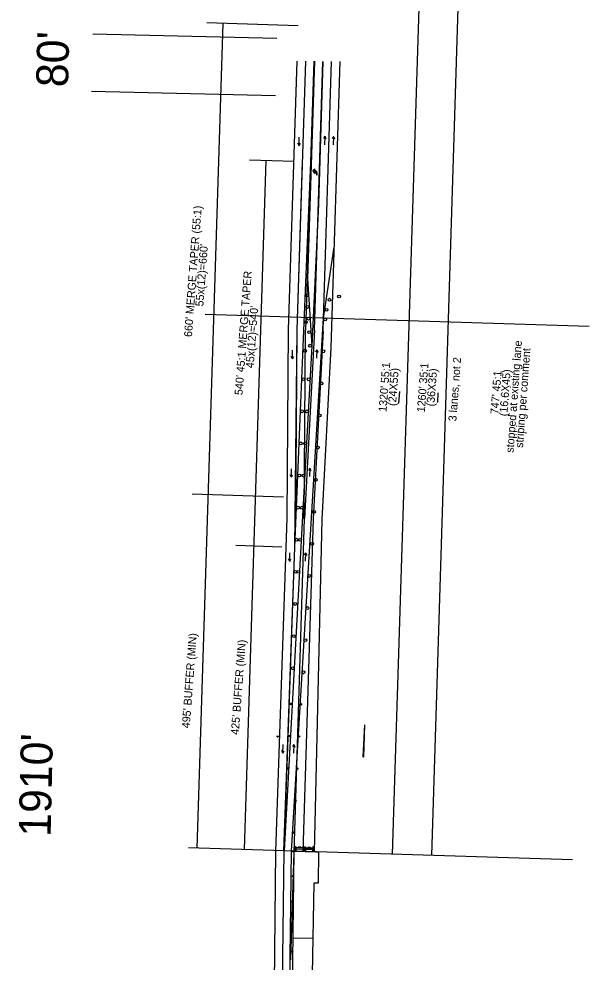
# Model space of a CAD drawing. Extents: x 1650647 to 1653016, y 602856 to 611467.
# Drawn here: x 1652184 to 1652982, y 608492 to 609813 of the extents above; entities that cross this region are included whole.
import ezdxf

# ---------------------------------------------------------------- set-up
doc = ezdxf.new("R2010")
doc.units = 0
for name, color, linetype in [('CM_Corridor_Design', 7, 'Continuous'), ('DT_X_Break_Line', 7, 'Continuous'), ('DT_X_Contour_Major', 7, 'Continuous'), ('DT_X_Void', 7, 'Continuous'), ('GE_P_Alignment_500_Bearings', 7, 'Continuous'), ('GE_P_Alignment_500_Stations', 7, 'Continuous'), ('PF_P_Grade_Line', 7, 'Continuous'), ('PF_X_Ground_Line', 7, 'Continuous'), ('PF_X_Ground_Line_LT', 7, 'Continuous'), ('PF_X_Ground_Line_RT', 7, 'Continuous'), ('PV_P_Curb', 7, 'Continuous'), ('PV_P_EOP', 7, 'Continuous'), ('PV_X_EOP', 7, 'Continuous'), ('SC_ProfileRun2', 7, 'Continuous'), ('SC_Scratch1', 7, 'Continuous'), ('UT_X_Water', 7, 'Continuous')]:
    doc.layers.add(name, color=color, linetype=linetype)

msp = doc.modelspace()

# ---------------------------------------------------------------- linework, layer by layer
at = {"layer": 'CM_Corridor_Design'}
for p, q in [((1652576.1, 609635.2), (1652576.3, 609647.1)), ((1652612, 609648.4), (1652610.1, 609645.1)), ((1652612, 609648.4), (1652611.5, 609636.5)), ((1652612, 609648.4), (1652613.6, 609644.9)), ((1652624.3, 609648.2), (1652622.4, 609644.9)), ((1652624.3, 609648.2), (1652623.8, 609636.3)), ((1652624.3, 609648.2), (1652625.9, 609644.8)), ((1652576.1, 609635.2), (1652574.4, 609638.6)), ((1652576.1, 609635.2), (1652577.9, 609638.6)), ((1652566.9, 609336.8), (1652565.2, 609340.2)), ((1652566.9, 609336.8), (1652566.8, 609348.7)), ((1652566.9, 609336.8), (1652568.6, 609340.2)), ((1652601, 609349.4), (1652599.2, 609346.1)), ((1652601, 609349.4), (1652600.5, 609337.6)), ((1652601, 609349.4), (1652602.6, 609346)), ((1652565.4, 609171.1), (1652565.3, 609182.9)), ((1652591.2, 609183.9), (1652589.3, 609180.6)), ((1652591.2, 609183.9), (1652590.7, 609172)), ((1652591.2, 609183.9), (1652592.8, 609180.4)), ((1652565.4, 609171.1), (1652563.7, 609174.4)), ((1652565.4, 609171.1), (1652567.1, 609174.5)), ((1652563, 609053.2), (1652563.4, 609065.1)), ((1652585.3, 609065.1), (1652583.4, 609061.8)), ((1652585.3, 609065.1), (1652584.8, 609053.3)), ((1652585.3, 609065.1), (1652586.9, 609061.7)), ((1652563, 609053.2), (1652561.4, 609056.7)), ((1652563, 609053.2), (1652564.8, 609056.6)), ((1652553.5, 608784.8), (1652554, 608796.7)), ((1652568.8, 608796.8), (1652566.9, 608793.5)), ((1652568.8, 608796.8), (1652568.3, 608784.9)), ((1652568.8, 608796.8), (1652570.4, 608793.3)), ((1652553.5, 608784.8), (1652551.9, 608788.3)), ((1652553.5, 608784.8), (1652555.4, 608788.2))]:
    msp.add_line(p, q, dxfattribs=at)
at = {"layer": 'DT_X_Break_Line'}
for centre, radius in [((1652587.1, 609425.7), 2), ((1652618.7, 609419.6), 2), ((1652632.1, 609424.1), 2), ((1652588.1, 609409.4), 2), ((1652614.4, 609405.4), 2), ((1652589.1, 609393.1), 2), ((1652612.5, 609392), 2), ((1652585.5, 609388.1), 2), ((1652590.3, 609374.1), 2), ((1652591.5, 609355.1), 2), ((1652584.3, 609348.2), 2), ((1652610, 609347.3), 2), ((1652582.1, 609308.3), 2), ((1652589.6, 609308.1), 2), ((1652607.4, 609302.4), 2), ((1652580.2, 609263.4), 2), ((1652587.2, 609263.2), 2), ((1652604.8, 609257.4), 2), ((1652578.4, 609218.4), 2), ((1652584.8, 609218.2), 2), ((1652602.2, 609212.5), 2), ((1652576.5, 609173.4), 2), ((1652582.3, 609173.3), 2), ((1652599.5, 609167.6), 2), ((1652574.6, 609128.5), 2), ((1652579.9, 609128.3), 2), ((1652596.9, 609122.6), 2), ((1652572.6, 609083.5), 2), ((1652577.5, 609083.4), 2), ((1652594.3, 609077.7), 2), ((1652571.1, 609038.6), 2), ((1652575, 609038.5), 2), ((1652590.3, 609032.8), 2), ((1652570.7, 608993.6), 2), ((1652587.7, 608987.9), 2), ((1652568.8, 608948.6), 2), ((1652585, 608942.9), 2), ((1652567.2, 608903.6), 2), ((1652582.4, 608898), 2), ((1652564.5, 608853.6), 1), ((1652578.7, 608853.1), 1), ((1652562.5, 608808.6), 1), ((1652576.2, 608808.2), 1), ((1652560.5, 608763.7), 1), ((1652573.5, 608763.2), 1), ((1652558.4, 608718.7), 1), ((1652570.9, 608718.3), 1), ((1652568.2, 608673.4), 1), ((1652567.8, 608647.5), 1), ((1652567.4, 608612.5), 1), ((1652567, 608577.5), 1), ((1652566.6, 608542.5), 1), ((1652566.2, 608507.5), 1)]:
    msp.add_circle(centre, radius, dxfattribs=at)
at = {"layer": 'DT_X_Contour_Major'}
msp.add_line((1652595.2, 608525.2), (1652567.8, 608525.6), dxfattribs=at)
msp.add_lwpolyline([(1652553.1, 607306.6), (1652569.1, 608647.5), (1652599.4, 608646.6), (1652603.4, 608646.5), (1652602.8, 608602.7), (1652596.7, 608602.8), (1652594.3, 608475.1)], dxfattribs=at)
at = {"layer": 'DT_X_Void'}
for p, q in [((1652598.3, 609602.3), (1652595.2, 609599.9)), ((1652597.5, 609600.1), (1652598.3, 609602.3)), ((1652598.3, 609602.3), (1652598.3, 609602.3)), ((1652595.2, 609599.9), (1652597.7, 609596.3)), ((1652598.2, 609600.1), (1652597.5, 609600.1)), ((1652597.7, 609596.3), (1652597.5, 609598.5)), ((1652597.5, 609598.5), (1652598.2, 609598.5)), ((1652598, 609594.3), (1652598, 609594.3)), ((1652600.4, 609596.1), (1652600.3, 609594.2)), ((1652600.3, 609594.2), (1652601.3, 609594.2)), ((1652601.3, 609594.2), (1652601.4, 609596.7)), ((1652581.8, 608652.1), (1652571.8, 608652.2)), ((1652574.8, 608653.7), (1652578.8, 608653.6)), ((1652575.8, 608652.2), (1652575.8, 608653.7)), ((1652576.8, 608651.2), (1652576.8, 608651.2)), ((1652577.8, 608652.2), (1652577.8, 608653.7)), ((1652595.2, 608651.7), (1652585.2, 608651.8)), ((1652588.2, 608653.3), (1652592.2, 608653.2)), ((1652589.2, 608651.8), (1652589.2, 608653.3)), ((1652591.2, 608651.7), (1652591.2, 608653.2)), ((1652581.8, 608650.1), (1652571.8, 608650.2)), ((1652595.1, 608649.7), (1652585.1, 608649.8)), ((1652590.1, 608650.8), (1652590.1, 608650.8))]:
    msp.add_line(p, q, dxfattribs=at)
for points in [[(1652570.8, 608648.2), (1652570.8, 608654.2), (1652571.8, 608654.2), (1652571.8, 608648.2)], [(1652582.8, 608648.1), (1652582.8, 608654.1), (1652581.8, 608654.1), (1652581.8, 608648.1)], [(1652584.1, 608647.8), (1652584.2, 608653.8), (1652585.2, 608653.8), (1652585.1, 608647.8)], [(1652596.1, 608647.7), (1652596.2, 608653.7), (1652595.2, 608653.7), (1652595.1, 608647.7)]]:
    msp.add_lwpolyline(points, close=True, dxfattribs=at)
for centre, radius, end in [((1652598.1, 609596.8), 3.28, 88.8321), ((1652598.1, 609596.2), 2.3, 87.9236)]:
    msp.add_arc(centre, radius, 357.9236, end, dxfattribs=at)
at = {"layer": 'GE_P_Alignment_500_Bearings'}
for p, q in [((1652588.5, 609448.9), (1652598, 609753.4)), ((1652594.5, 609355), (1652588.5, 609448.9)), ((1652555.8, 608648), (1652594.5, 609355))]:
    msp.add_line(p, q, dxfattribs=at)
for points in [[(1652570.2, 609072.8), (1652592.6, 609612.3), (1652597, 609753.4)], [(1652554.8, 608648), (1652560.7, 608815.3), (1652570.2, 609072.8)]]:
    msp.add_lwpolyline(points, dxfattribs=at)
at = {"layer": 'GE_P_Alignment_500_Stations'}
msp.add_line((1652594.5, 609355), (1652603.8, 609553.2), dxfattribs=at)
msp.add_lwpolyline([(1652570.2, 609072.7), (1652573.3, 609377.2), (1652580.9, 609612.7)], dxfattribs=at)
at = {"layer": 'PF_P_Grade_Line'}
for p, q in [((1652573.3, 609377.2), (1652585.5, 609753.5)), ((1652609.8, 609377.1), (1652621.5, 609753)), ((1652571.7, 609113.5), (1652573.3, 609377.2)), ((1652596.4, 609112.7), (1652610.3, 609376.1)), ((1652555.3, 608647.1), (1652571.7, 609113.5)), ((1652581.9, 608647.2), (1652596.4, 609112.7))]:
    msp.add_line(p, q, dxfattribs=at)
at = {"layer": 'PF_X_Ground_Line'}
for p, q in [((1652547.6, 608808.1), (1652544.4, 608808.2)), ((1652546, 608808.2), (1652545.9, 608806.6)), ((1652546, 608808.2), (1652546, 608808.2))]:
    msp.add_line(p, q, dxfattribs=at)
at = {"layer": 'PF_X_Ground_Line_LT'}
msp.add_line((1652585.8, 609377.1), (1652597.5, 609753.3), dxfattribs=at)
at = {"layer": 'PF_X_Ground_Line_RT'}
for p, q in [((1652707.1, 608643.3), (1652748.3, 609962.6)), ((1652761.8, 608641.6), (1652801.2, 609901)), ((1652433.6, 608651.8), (1652469.7, 609806.2)), ((1652575, 609803), (1652446.9, 609807)), ((1652569.1, 609613.1), (1652506.9, 609615)), ((1652499.7, 608649.8), (1652529.9, 609614.3)), ((1652982.1, 609382.1), (1652444.8, 609398.9)), ((1652715.7, 609274.7), (1652717.1, 609291.1)), ((1652770.4, 609275.5), (1652770.6, 609289.3)), ((1652554.4, 609143.3), (1652426.3, 609147.3)), ((1652552.2, 609073.3), (1652487.6, 609075.4)), ((1652665.6, 608779.4), (1652668.2, 608824.3)), ((1652666.6, 608779.3), (1652668.2, 608824.3)), ((1652666.6, 608779.3), (1652665.6, 608779.4)), ((1652958.8, 608635.4), (1652421.5, 608652.2))]:
    msp.add_line(p, q, dxfattribs=at)
at = {"layer": 'PV_P_Curb'}
for p, q in [((1652583.4, 609113.3), (1652585.3, 609377.1)), ((1652584.4, 609113.3), (1652598.3, 609376.7)), ((1652564.6, 608495.4), (1652583.9, 609113.3))]:
    msp.add_line(p, q, dxfattribs=at)
at = {"layer": 'PV_P_EOP'}
for p, q in [((1652603.8, 609553.2), (1652610, 609753.2)), ((1652610.3, 609393.7), (1652625.2, 609493)), ((1652565.3, 608647.7), (1652610.3, 609393.7)), ((1652549, 607300.9), (1652565.3, 608647.7))]:
    msp.add_line(p, q, dxfattribs=at)
at = {"layer": 'PV_X_EOP'}
msp.add_line((1652539, 607301.1), (1652555.3, 608648), dxfattribs=at)
at = {"layer": 'SC_ProfileRun2'}
msp.add_line((1652597.8, 609376.7), (1652609.5, 609753.2), dxfattribs=at)
at = {"layer": 'SC_Scratch1'}
for p, q in [((1652561.3, 609377.3), (1652573.5, 609753.6)), ((1652621.1, 609352.5), (1652633.5, 609752.9)), ((1652559.4, 609113.5), (1652561.3, 609377.3)), ((1652608.4, 609112), (1652621.1, 609352.5)), ((1652543.8, 608647.3), (1652559.4, 609113.5)), ((1652597.8, 608646.6), (1652608.4, 609112)), ((1652527.5, 607301.2), (1652543.8, 608647.3))]:
    msp.add_line(p, q, dxfattribs=at)
at = {"layer": 'UT_X_Water'}
for p, q in [((1652544.8, 609785.2), (1652287.4, 609791.2)), ((1652543, 609705.2), (1652285.5, 609711.2))]:
    msp.add_line(p, q, dxfattribs=at)

# ---------------------------------------------------------------- texts
at = {"layer": 'PF_X_Ground_Line_RT'}
for s, p in [("660' MERGE TAPER (55:1)", (1652426.1, 609367.1)), ("55x(12)=660'", (1652442, 609409.9)), ("540' 45:1 MERGE TAPER", (1652496.9, 609285.7)), ("45x(12)=540'", (1652512.4, 609323.4)), ('stopped at existing lane', (1652876.3, 609205.1)), ('striping per comment', (1652889.5, 609211.9)), ('3 lanes, not 2', (1652796.2, 609248.9)), ("1320' 55:1", (1652698.5, 609262.2)), ("1260' 35:1", (1652752.1, 609261.6)), ('(24X55)', (1652711.7, 609270.5)), ('(36X35)', (1652765.4, 609269.9)), ("747' 45:1", (1652855.1, 609258.9)), ('(16.6X45)', (1652867.5, 609256.1)), ("495' BUFFER (MIN)", (1652423, 608819.3)), ("425' BUFFER (MIN)", (1652491.6, 608810.1))]:
    msp.add_text(s, height=11.2, rotation=85.6823, dxfattribs=at).set_placement(p)
at = {"layer": 'UT_X_Water'}
for s, p in [("80'", (1652252.7, 609716.7)), ("1910'", (1652228.3, 608667.2))]:
    msp.add_text(s, height=44.8, rotation=88.672, dxfattribs=at).set_placement(p)

doc.saveas('drawing.dxf')
